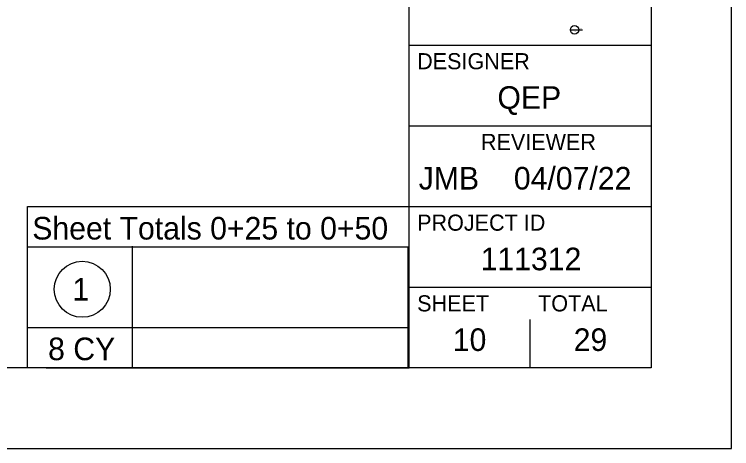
# Model space of a CAD drawing. Extents: x -149 to 34, y 0 to 22.
# Drawn here: x 29.553 to 34, y 0 to 2.69 of the extents above; entities that cross this region are included whole.
import ezdxf

# ---------------------------------------------------------------- set-up
doc = ezdxf.new("R2010")
doc.units = 0
for name, color, linetype in [('CS-ALGN-TEXT', 7, 'Continuous'), ('CS-ANNO', 7, 'Continuous'), ('CS-ANNO-MATC', 7, 'Continuous'), ('CS-ANNO-MATC-TEXT', 7, 'Continuous'), ('CS-ANNO-TABL', 7, 'Continuous')]:
    doc.layers.add(name, color=color, linetype=linetype)

msp = doc.modelspace()

# ---------------------------------------------------------------- linework, layer by layer
at = {"layer": 'CS-ALGN-TEXT'}
for p, q in [((29.6338, 0.5), (29.6338, 1.5)), ((29.6338, 1.5), (32, 1.5)), ((29.6338, 1.25), (32, 1.25)), ((31.995, 0.4999), (31.995, 1.2499)), ((32.75, 0.5), (32.75, 0.8)), ((29.6338, 0.75), (32, 0.75)), ((32.375, 0.675), (32.375, 0.675)), ((29.75, 0.5), (32, 0.5))]:
    msp.add_line(p, q, dxfattribs=at)
at = {"layer": 'CS-ANNO'}
msp.add_lwpolyline([(0, 0), (34, 0), (34, 22), (0, 22)], close=True, dxfattribs=at)
at = {"layer": 'CS-ANNO-MATC'}
for p, q in [((32, 0.5), (32, 21.5)), ((32, 2.5), (33.5, 2.5)), ((32, 2), (33.5, 2)), ((32, 1.5), (33.5, 1.5)), ((32, 1), (33.5, 1))]:
    msp.add_line(p, q, dxfattribs=at)
msp.add_lwpolyline([(1.5, 21.5), (33.5, 21.5), (33.5, 0.5), (1.5, 0.5)], close=True, dxfattribs=at)
at = {"layer": 'CS-ANNO-MATC-TEXT'}
msp.add_line((30.2834, 1.2548), (30.2834, 0.5048), dxfattribs=at)
msp.add_circle((29.974, 0.9873), 0.1737, dxfattribs=at)
at = {"layer": 'CS-ANNO-TABL'}
for p, q in [((33.0001, 2.5945), (33.0522, 2.5945)), ((33.0264, 2.5945), (33.0759, 2.5945))]:
    msp.add_line(p, q, dxfattribs=at)
msp.add_circle((33.0262, 2.5945), 0.026, dxfattribs=at)

# ---------------------------------------------------------------- texts
at = {"layer": 'CS-ALGN-TEXT'}
for s, height, p in [('DESIGNER', 0.1, (32.05, 2.35)), ('QEP', 0.14, (32.5477, 2.105)), ('REVIEWER', 0.1, (32.4454, 1.85)), ('JMB', 0.14, (32.0596, 1.605)), ('04/07/22', 0.14, (32.6497, 1.605)), ('Sheet Totals 0+25 to 0+50', 0.14, (29.6636, 1.2953)), ('PROJECT ID', 0.1, (32.05, 1.35)), ('111312', 0.14, (32.4435, 1.105)), ('SHEET', 0.1, (32.05, 0.85)), ('TOTAL', 0.1, (32.8, 0.85)), ('10', 0.14, (32.271, 0.605)), ('29', 0.14, (33.0206, 0.605))]:
    msp.add_text(s, height=height, dxfattribs=at).set_placement(p)
at = {"layer": 'CS-ANNO-MATC-TEXT'}
for s, p in [('1', (29.9128, 0.9171)), ('8 CY', (29.7619, 0.5479))]:
    msp.add_text(s, height=0.14, dxfattribs=at).set_placement(p)
at = {"layer": 'CS-ANNO-TABL'}
for s, p in [('0+25.00', (33.0181, 2.5847)), ('3', (33.025, 2.6011)), ('Drawing', (33.0589, 2.6011)), ('1:2', (33.0589, 2.5847))]:
    msp.add_text(s, height=0.00328, dxfattribs=at).set_placement(p)

doc.saveas('drawing.dxf')
